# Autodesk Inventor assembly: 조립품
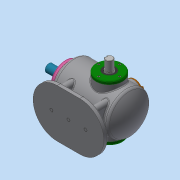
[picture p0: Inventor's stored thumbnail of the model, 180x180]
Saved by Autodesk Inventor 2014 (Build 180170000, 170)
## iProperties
Created: 2022-08
Part Number: 조립품
Document SubType Name: Assembly
Designer: dg
Mass: 8316.85 g
Surface Area: 4266.62 cm^2
Volume: 2093.19 cm^3
Density: 3.97329 g/cm^3
Author: dg
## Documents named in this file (16)
- C:\Users\dg\Desktop\620806V1007\조립품.iam
- C:\Users\dg\Desktop\620806V1007\플레이트.ipt
- C:\Users\dg\Desktop\620806V1007\본체.ipt
- C:\Users\dg\Desktop\620806V1007\편심축.ipt
- C:\Users\dg\Desktop\620806V1007\베어링 6205.ipt
- 베어링 6205.ipt
- C:\Users\dg\Desktop\620806V1007\축 커버-1.ipt
- C:\Users\dg\Desktop\620806V1007\오일실.ipt
- 오일실.ipt
- C:\Users\dg\Desktop\620806V1007\축 커버-2.ipt
- C:\Users\dg\Desktop\620806V1007\슬라이드.ipt
- C:\Users\dg\Desktop\620806V1007\가변스프링.ipt
- C:\Users\dg\Desktop\620806V1007\부시.ipt
- C:\Users\dg\Desktop\620806V1007\슬라이드 커버.ipt
- C:\Users\dg\Desktop\620806V1007\상부 캡.ipt
- C:\Users\dg\Desktop\620806V1007\볼트 M4x0.7.ipt
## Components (14 placed, 3 different names)
1. 플레이트:1
2. 가변스프링:1
3. M4x0.7:1
4. M4x0.7:2
5. M4x0.7:3
6. M4x0.7:4
7. M4x0.7:5
8. M4x0.7:6
9. M4x0.7:7
10. M4x0.7:8
11. M4x0.7:9
12. M4x0.7:10
13. M4x0.7:11
14. M4x0.7:12
